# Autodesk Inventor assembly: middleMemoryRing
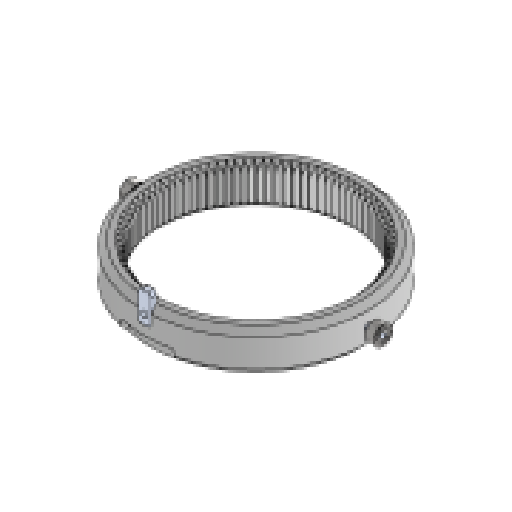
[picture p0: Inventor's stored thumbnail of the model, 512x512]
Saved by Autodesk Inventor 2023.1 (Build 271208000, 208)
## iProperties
Created: 2021-02
Part Number: middleMemoryRing
Document SubType Name: Assembly
Designer: ftrauzettel
Author: ftrauzettel
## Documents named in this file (6)
- C:\Users\Fabian\OneDrive\Delft\CPMM\Machined_Prototype\Mods\Assemblies\subAssemblies\middleMemoryRing.iam
- C:\Users\Fabian\OneDrive\Delft\CPMM\Machined_Prototype\Mods\Parts\original parts\Memory ring.ipt
- C:\Users\Fabian\OneDrive\Delft\CPMM\Machined_Prototype\Mods\Parts\original parts\Pin 1.ipt
- C:\Users\Fabian\OneDrive\Delft\CPMM\Machined_Prototype\Mods\Parts\original parts\Fastening pin.ipt
- C:\Users\Fabian\OneDrive\Delft\CPMM\Machined_Prototype\Mods\Parts\original parts\Bearing pin.ipt
- C:\Users\Fabian\OneDrive\Delft\CPMM\Machined_Prototype\Mods\ContentCenter\en-US\ISO 1224-1 M\ISO 1224-1 - 38 - 1 x 3 x 1.5.ipt
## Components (7 placed, 5 different names)
1. Memory ring:1 — Mate:1, Mate:2, Mate:3, Mate:5, Mate:6, Mate:7, Mate:8
2. Pin 1:1 — Mate:1, Mate:2, Mate:4
3. Fastening pin:1 — Mate:3, Mate:4
4. Bearing pin:1 — Mate:5, Mate:6, Mate:9, Flush:1
5. Bearing pin:2 — Mate:7, Mate:8, Flush:11, Mate:10
6. ISO 1224-1 (Metric) 38 - 1 x 3 x 1.5:1 — Flush:11, Mate:10
7. ISO 1224-1 (Metric) 38 - 1 x 3 x 1.5:2 — Mate:9, Flush:1
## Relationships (12: Mate 10, Flush 2)
- Mate:1: Memory ring:1 ↔ Pin 1:1
- Mate:2: Memory ring:1 ↔ Pin 1:1
- Mate:3: Memory ring:1 ↔ Fastening pin:1
- Mate:4: Pin 1:1 ↔ Fastening pin:1
- Mate:5: Memory ring:1 ↔ Bearing pin:1
- Mate:6: Memory ring:1 ↔ Bearing pin:1
- Mate:7: Memory ring:1 ↔ Bearing pin:2
- Mate:8: Memory ring:1 ↔ Bearing pin:2
- Mate:9: Bearing pin:1 ↔ ISO 1224-1 (Metric) 38 - 1 x 3 x 1.5:2
- Flush:1: Bearing pin:1 ↔ ISO 1224-1 (Metric) 38 - 1 x 3 x 1.5:2
- Flush:11: Bearing pin:2 ↔ ISO 1224-1 (Metric) 38 - 1 x 3 x 1.5:1
- Mate:10: Bearing pin:2 ↔ ISO 1224-1 (Metric) 38 - 1 x 3 x 1.5:1
